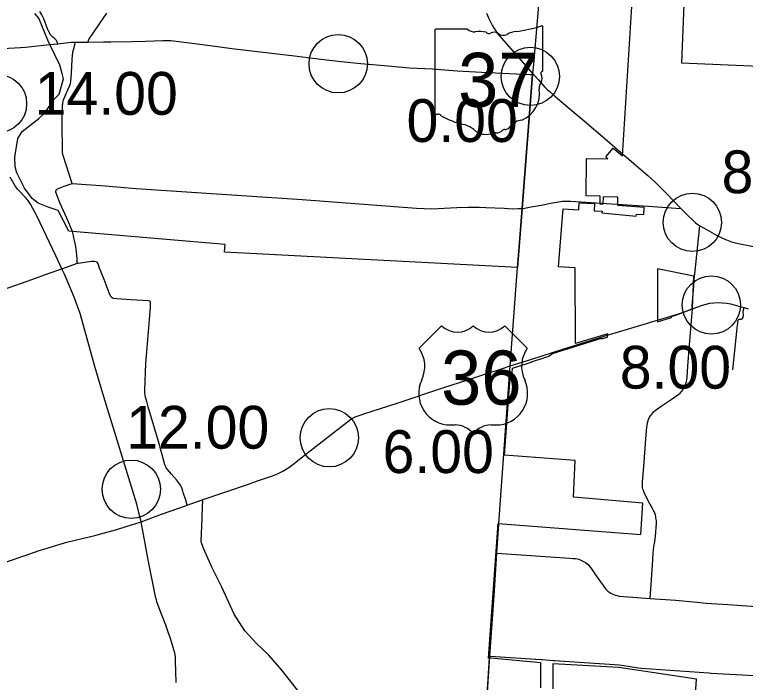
# Model space of a CAD drawing. Extents: x 1597222 to 1925846, y 496284 to 911751.
# Drawn here: x 1780898 to 1799698, y 830013 to 847184 of the extents above; entities that cross this region are included whole.
import ezdxf

# ---------------------------------------------------------------- set-up
doc = ezdxf.new("R2010")
doc.units = 0
for name, color, linetype in [('Default', 7, 'Continuous'), ('GM_X_City_Street', 7, 'Continuous'), ('GM_X_Corporation', 7, 'Continuous'), ('GM_X_County_Road', 7, 'Continuous'), ('GM_X_State_Route', 7, 'Continuous'), ('GM_X_State_Shield', 7, 'Continuous'), ('GM_X_Township', 7, 'Continuous'), ('GM_X_Township_Road', 7, 'Continuous'), ('GM_X_US_Route', 7, 'Continuous'), ('GM_X_US_Shield', 7, 'Continuous')]:
    doc.layers.add(name, color=color, linetype=linetype)

msp = doc.modelspace()

# ---------------------------------------------------------------- linework, layer by layer
at = {"layer": 'Default'}
for centre in [(1789222, 845920), (1794166, 845595), (1780458, 844894), (1798335, 841842), (1798823, 839718), (1788994, 836303), (1783899, 834980)]:
    msp.add_circle(centre, 750, dxfattribs=at)
at = {"layer": 'GM_X_City_Street'}
for points in [[(1797209, 842260), (1797313, 842248), (1798035, 842200)], [(1798391, 840480), (1798393, 840510), (1798525, 841754)], [(1797247, 832172), (1797308, 833027), (1797327, 833333), (1797341, 833506), (1797367, 833630), (1797385, 833772), (1797411, 834102), (1797410, 834129), (1797409, 834165), (1797403, 834211), (1797397, 834244), (1797390, 834277), (1797383, 834312), (1797374, 834341), (1797357, 834387), (1797336, 834430), (1797307, 834485), (1797208, 834668), (1797135, 834807), (1797094, 834887), (1797073, 834944), (1797063, 834978), (1797055, 835013), (1797051, 835044), (1797048, 835076), (1797048, 835124), (1797051, 835173), (1797082, 835564), (1797140, 836270), (1797162, 836583), (1797170, 836630), (1797176, 836667), (1797183, 836695), (1797196, 836742), (1797207, 836777), (1797219, 836804), (1797233, 836833), (1797248, 836861), (1797265, 836886), (1797288, 836914), (1797313, 836944), (1797338, 836971), (1797374, 837003), (1797407, 837026), (1797534, 837113), (1797816, 837304), (1797982, 837420), (1798018, 837451), (1798045, 837481), (1798068, 837511), (1798088, 837537), (1798108, 837569), (1798132, 837611), (1798147, 837650), (1798166, 837697), (1798185, 837753), (1798193, 837803), (1798199, 837862), (1798219, 838143), (1798256, 838693), (1798334, 839621)], [(1798334, 839621), (1798331, 839671)], [(1799374, 838047), (1799488, 839118), (1799511, 839323), (1799525, 839347), (1799540, 839354), (1799586, 839357), (1799611, 839361), (1799640, 839398), (1799646, 839456), (1799643, 839557), (1799664, 839649)], [(1793120, 830695), (1793232, 832236), (1793303, 833333), (1793351, 834085)], [(1793303, 833333), (1795175, 833207), (1795258, 833200), (1795331, 833194), (1795377, 833186), (1795411, 833177), (1795450, 833165), (1795485, 833150), (1795520, 833133), (1795550, 833116), (1795584, 833095), (1795621, 833066), (1795649, 833041), (1795673, 833015), (1795735, 832935), (1795861, 832755), (1796037, 832503), (1796074, 832453), (1796109, 832412), (1796137, 832383), (1796162, 832362), (1796185, 832343), (1796207, 832326), (1796232, 832310), (1796267, 832291), (1796301, 832276), (1796344, 832258), (1796395, 832244), (1796451, 832232), (1796564, 832223), (1796677, 832214), (1796800, 832206), (1797247, 832172), (1797901, 832125), (1798456, 832073), (1798693, 832053), (1799244, 832014), (1800095, 831955)], [(1794436, 830599), (1794466, 830597), (1794751, 830577)], [(1797010, 830375), (1797016, 830374), (1798754, 830257), (1798814, 830253), (1801541, 830101)]]:
    msp.add_lwpolyline(points, dxfattribs=at)
at = {"layer": 'GM_X_Corporation'}
for points in [[(1794432, 829873), (1794432, 830514), (1793153, 830634), (1793153, 830626), (1793093, 830632), (1793335, 834100), (1797009, 833813), (1797057, 834620), (1795274, 834775), (1795316, 835721), (1793499, 835852), (1793659, 837976), (1793698, 837973), (1793707, 838091), (1794085, 838213), (1794212, 838252), (1794209, 838262), (1794434, 838332), (1794637, 838403), (1794733, 838467), (1794733, 838467), (1795997, 838865), (1795996, 838844), (1796153, 838890), (1796155, 838973), (1795326, 838724), (1795319, 840669), (1794894, 840702), (1795009, 842190), (1795409, 842166), (1795420, 842348), (1795817, 842324), (1795804, 842142), (1796013, 842128), (1796009, 842085), (1796891, 842003), (1796893, 842053), (1797088, 842046), (1797094, 842227), (1796414, 842277), (1796416, 842493), (1796036, 842499), (1796033, 842307), (1795958, 842309), (1795961, 842515), (1795598, 842521), (1795613, 843484), (1796162, 843475), (1796105, 843523), (1796297, 843753), (1796540, 843550), (1796878, 849051)], [(1798177, 848946), (1798053, 845944), (1800661, 845836)], [(1798334, 828546), (1798442, 830097), (1796442, 830397), (1794748, 830490), (1794748, 829844)]]:
    msp.add_lwpolyline(points, dxfattribs=at)
msp.add_lwpolyline([(1797441, 839284), (1797798, 839399), (1797801, 839422), (1797912, 839458), (1798198, 839567), (1798339, 839626), (1798371, 840459), (1797440, 840649)], close=True, dxfattribs=at)
at = {"layer": 'GM_X_County_Road'}
for points in [[(1782794, 846480), (1782798, 846516), (1782808, 846543), (1783085, 846950), (1783272, 847226)], [(1793847, 840780), (1793954, 842199), (1794218, 845643)], [(1782409, 841508), (1782391, 841606), (1782242, 841946), (1782072, 842331), (1781962, 842618), (1781962, 842650), (1781965, 842662), (1781975, 842683), (1782000, 842708), (1782174, 842776), (1782382, 842844), (1783229, 842784), (1784027, 842716), (1788298, 842429), (1791241, 842207), (1791633, 842186), (1792271, 842228), (1792567, 842237), (1792853, 842229), (1793017, 842224), (1793496, 842204), (1793598, 842199), (1793716, 842194), (1793856, 842196), (1793901, 842196), (1793954, 842199)], [(1793954, 842199), (1794020, 842207), (1794133, 842230), (1794444, 842288), (1794735, 842342), (1794989, 842386), (1795095, 842389), (1795206, 842386), (1795597, 842359), (1796522, 842302), (1796538, 842301)], [(1796538, 842301), (1796781, 842284), (1797209, 842260)], [(1782516, 840796), (1782504, 840822), (1782504, 840849), (1782503, 840907), (1782496, 840999), (1782473, 841224), (1782437, 841372), (1782421, 841443), (1782409, 841508)], [(1782111, 840650), (1782111, 840650), (1782516, 840796)], [(1793647, 838152), (1793839, 840685), (1793847, 840780)], [(1779079, 839573), (1781342, 840372), (1781765, 840527), (1782111, 840650)], [(1798331, 839671), (1798329, 839693), (1798369, 840209), (1798391, 840480)], [(1793351, 834085), (1793352, 834099), (1793647, 838152)], [(1792915, 827504), (1793116, 830642)], [(1793116, 830642), (1793120, 830695)], [(1793120, 830695), (1793142, 830690), (1794436, 830599)], [(1794751, 830577), (1794787, 830575), (1796457, 830461), (1797010, 830375)]]:
    msp.add_lwpolyline(points, dxfattribs=at)
at = {"layer": 'GM_X_State_Route'}
for points in [[(1794187, 845719), (1793434, 846579), (1793324, 846710), (1793274, 846777), (1793187, 846924), (1793100, 847093), (1793045, 847210)], [(1780260, 846299), (1780260, 846299), (1781047, 846338), (1781176, 846347), (1781331, 846363), (1781806, 846413), (1782009, 846435), (1782350, 846472), (1782467, 846475), (1782747, 846479)], [(1782747, 846479), (1782794, 846480), (1783183, 846484), (1783377, 846485), (1783923, 846492), (1784269, 846503), (1784713, 846520), (1784920, 846517), (1785189, 846487), (1785532, 846441), (1785928, 846388), (1786488, 846310), (1787292, 846217), (1788027, 846133), (1788780, 846042), (1789296, 845980), (1789805, 845926), (1790403, 845872), (1791058, 845819), (1791646, 845786), (1792283, 845741), (1792907, 845707), (1794165, 845645)], [(1794165, 845645), (1794218, 845643), (1794256, 845640)], [(1794256, 845640), (1794225, 845677), (1794187, 845719)], [(1794256, 845640), (1794372, 845506), (1794532, 845328), (1794610, 845252), (1794673, 845195), (1794795, 845090), (1795070, 844854), (1795139, 844795), (1795501, 844493), (1796141, 843947), (1796409, 843716), (1796609, 843541)], [(1796609, 843541), (1796627, 843525), (1796897, 843295), (1796897, 843295)], [(1796897, 843295), (1797184, 843049), (1797375, 842873), (1797459, 842793), (1797671, 842582), (1798035, 842200), (1798181, 842051), (1798372, 841875), (1798417, 841833), (1798475, 841788), (1798525, 841754), (1798715, 841646), (1798952, 841516), (1799123, 841431), (1799251, 841372), (1799337, 841343), (1799378, 841331), (1799477, 841307), (1799775, 841246), (1800109, 841182)], [(1782426, 839915), (1782250, 840350), (1782172, 840527), (1782111, 840650), (1781955, 840981), (1781476, 841997), (1781310, 842306), (1781236, 842414), (1781182, 842481), (1780990, 842678), (1780970, 842699), (1780952, 842720), (1780919, 842766), (1780783, 843002)], [(1785057, 830010), (1785050, 830079), (1785047, 830234), (1785036, 830617), (1785033, 830668), (1785019, 830761), (1784998, 830853), (1784946, 831027), (1784900, 831165), (1784850, 831306), (1784785, 831484), (1784615, 831925), (1784558, 832087), (1784544, 832136), (1784524, 832218), (1784335, 833168), (1784151, 834144), (1784039, 834594), (1783197, 837352), (1782964, 838137), (1782587, 839495), (1782452, 839852), (1782426, 839915)]]:
    msp.add_lwpolyline(points, dxfattribs=at)
at = {"layer": 'GM_X_State_Shield'}
for p, q in [((1791706, 846774), (1791706, 844660)), ((1791706, 846774), (1791706, 844660)), ((1792549, 846810), (1791733, 846810)), ((1792549, 846810), (1791733, 846810)), ((1794490, 845757), (1794490, 846862)), ((1794490, 845757), (1794490, 846862)), ((1794490, 845757), (1794490, 845757)), ((1794490, 845757), (1794490, 845757))]:
    msp.add_line(p, q, dxfattribs=at)
for centre, radius, start, end in [((1791738, 846778), 32.3, 98.1301, 188.1301), ((1791738, 846778), 32.3, 98.1301, 188.1301), ((1792743, 847055), 313, 231.6195, 271.1119), ((1792743, 847055), 313, 231.6195, 271.1119), ((1792846, 845624), 1123, 80.4867, 94.9883), ((1792846, 845624), 1123, 80.4867, 94.9883), ((1793875, 846165), 594, 97.3462, 120.7689), ((1793875, 846165), 594, 97.3462, 120.7689), ((1793498, 849691), 2953, 275.8445, 288.9065), ((1793498, 849691), 2953, 275.8445, 288.9065), ((1794459, 846867), 31, 351.8621, 97.738), ((1794459, 846867), 31, 351.8621, 97.738), ((1793101, 846789), 90.3, 219.7921, 297.1024), ((1793101, 846789), 90.3, 219.7921, 297.1024), ((1793234, 846545), 188, 54.4667, 119.1411), ((1793234, 846545), 188, 54.4667, 119.1411), ((1793476, 846880), 226, 233.8562, 294.8282), ((1793476, 846880), 226, 233.8562, 294.8282), ((1794483, 845676), 48, 107.944, 210.337), ((1794483, 845676), 48, 107.944, 210.337), ((1794178, 845536), 288, 340.033, 23.6496), ((1794178, 845536), 288, 340.033, 23.6496), ((1794457, 845753), 33.2, 289.6038, 7.7341), ((1794457, 845753), 33.2, 289.6038, 7.7341), ((1794601, 845294), 210, 136.8065, 186.9296), ((1794601, 845294), 210, 136.8065, 186.9296), ((1793664, 845154), 739, 292.3089, 8.9858), ((1793664, 845154), 739, 292.3089, 8.9858), ((1791738, 844656), 32.5, 171.9584, 258.3066), ((1791738, 844656), 32.5, 171.9584, 258.3066), ((1791743, 844872), 248, 267.339, 280.6039), ((1791743, 844872), 248, 267.339, 280.6039), ((1791794, 844539), 89.5, 29.7484, 93.2717), ((1791794, 844539), 89.5, 29.7484, 93.2717), ((1792924, 846437), 2132, 240.4129, 257.1985), ((1792924, 846437), 2132, 240.4129, 257.1985), ((1792288, 843711), 667, 47.1842, 75.836), ((1792288, 843711), 667, 47.1842, 75.836), ((1793463, 844456), 239, 282.8732, 323.2771), ((1793463, 844456), 239, 282.8732, 323.2771), ((1793975, 844067), 404, 94.4031, 142.5768), ((1793975, 844067), 404, 94.4031, 142.5768), ((1793010, 844528), 423, 230.7004, 286.2918), ((1793010, 844528), 423, 230.7004, 286.2918), ((1793255, 843797), 348, 85.6951, 111.2099), ((1793255, 843797), 348, 85.6951, 111.2099), ((1793286, 844370), 226, 268.777, 315.5493), ((1793286, 844370), 226, 268.777, 315.5493), ((1793490, 844165), 63.5, 65.7517, 132.6484), ((1793490, 844165), 63.5, 65.7517, 132.6484)]:
    msp.add_arc(centre, radius, start, end, dxfattribs=at)
at = {"layer": 'GM_X_Township'}
for points in [[(1794528, 849265), (1794250, 845913), (1794225, 845677), (1794218, 845643), (1793954, 842199), (1793839, 840685), (1786300, 841075), (1786314, 841270), (1782391, 841606), (1782290, 841614), (1782021, 842150), (1781758, 842232), (1781508, 842340), (1781351, 842454), (1781155, 842721), (1780952, 843117), (1780916, 843270), (1780907, 843520), (1780980, 844003), (1781094, 844181), (1781518, 844515), (1781682, 844666), (1781918, 845013), (1782045, 845142), (1782155, 845534), (1782125, 845674), (1782062, 845883), (1781806, 846413), (1781752, 846525), (1781519, 847094), (1781420, 847210)], [(1792915, 827502), (1793120, 830695), (1793232, 832236), (1793303, 833333), (1793352, 834099), (1793647, 838152), (1793839, 840685)]]:
    msp.add_lwpolyline(points, dxfattribs=at)
at = {"layer": 'GM_X_Township_Road'}
for points in [[(1782009, 846435), (1781994, 846482), (1781973, 846515), (1781956, 846538), (1781929, 846565), (1781890, 846597), (1781839, 846644), (1781814, 846675), (1781792, 846718), (1781744, 846822), (1781649, 847077), (1781600, 847179), (1781548, 847266)], [(1782382, 842844), (1782151, 843564), (1782126, 843641), (1782122, 844417), (1782128, 844831), (1782131, 844863), (1782135, 844894), (1782148, 844956), (1782159, 844992), (1782295, 845310), (1782307, 845335), (1782325, 845387), (1782332, 845413), (1782342, 845467), (1782359, 845678), (1782380, 846027), (1782397, 846217), (1782411, 846275), (1782467, 846475)], [(1785341, 834572), (1785304, 834696), (1785235, 834898), (1785228, 834929), (1785208, 834991), (1785183, 835051), (1785168, 835080), (1785144, 835122), (1785062, 835221), (1784931, 835371), (1784829, 835487), (1784800, 835530), (1784787, 835552), (1784776, 835576), (1784765, 835603), (1784625, 836119), (1784338, 837095), (1784296, 837239), (1784255, 837382), (1784244, 837484), (1784244, 837528), (1784276, 838215), (1784330, 838924), (1784391, 839658), (1784395, 839783), (1784389, 839805), (1784374, 839815), (1784341, 839823), (1783889, 839850), (1783530, 839873), (1783431, 839887), (1783405, 839902), (1783381, 839921), (1783363, 839952), (1783330, 840034), (1783198, 840371), (1783084, 840668), (1783045, 840772), (1783019, 840816), (1782989, 840831), (1782941, 840838), (1782879, 840837), (1782530, 840785), (1782516, 840796)], [(1788621, 827994), (1788650, 828063), (1788726, 828178), (1788739, 828252), (1788721, 828512), (1788707, 828711), (1788718, 828879), (1788680, 829037), (1788510, 829354), (1788376, 829562), (1787776, 830325), (1787442, 830711), (1787118, 831016), (1786817, 831334), (1786550, 831763), (1786230, 832458), (1785968, 832975), (1785767, 833439), (1785710, 833597), (1785701, 833646), (1785722, 834226), (1785735, 834569), (1785736, 834651), (1785723, 834708)]]:
    msp.add_lwpolyline(points, dxfattribs=at)
at = {"layer": 'GM_X_US_Route'}
for points in [[(1797279, 839280), (1797440, 839329), (1797949, 839483), (1798026, 839508), (1798154, 839553), (1798334, 839621)], [(1798334, 839621), (1798449, 839665), (1798596, 839716), (1798693, 839742), (1798786, 839760), (1798883, 839772), (1799014, 839778), (1799098, 839777), (1799221, 839764), (1799313, 839748), (1799413, 839724), (1799529, 839690), (1799664, 839649), (1799768, 839617)], [(1796520, 839053), (1796580, 839071), (1797177, 839250)], [(1797177, 839250), (1797279, 839280)], [(1796115, 838930), (1796520, 839053)], [(1794201, 838327), (1794977, 838574), (1796065, 838914)], [(1796065, 838914), (1796113, 838930), (1796115, 838930)], [(1793596, 838135), (1793647, 838152), (1794201, 838327)], [(1793294, 838037), (1793503, 838105), (1793596, 838135)], [(1785291, 834555), (1785341, 834572), (1785723, 834708), (1786913, 835110), (1787149, 835192), (1787535, 835324), (1787660, 835373), (1787802, 835441), (1787953, 835536), (1788092, 835640), (1788316, 835821), (1788577, 836027), (1789200, 836511), (1789464, 836715), (1789512, 836752), (1789559, 836786), (1789581, 836800), (1789608, 836815), (1789657, 836839), (1789708, 836860), (1789760, 836879), (1789880, 836917), (1790713, 837188), (1791944, 837592), (1792535, 837787), (1793152, 837991), (1793294, 838037)], [(1784151, 834144), (1784673, 834334), (1785291, 834555)], [(1781140, 833266), (1781530, 833400), (1781652, 833441), (1782073, 833569), (1782240, 833615), (1782816, 833759), (1782964, 833793), (1783306, 833880), (1783524, 833942), (1783770, 834017), (1784151, 834144)], [(1773271, 830397), (1773379, 830444), (1774387, 830877), (1775615, 831340), (1776007, 831488), (1777883, 832171), (1778258, 832305), (1778909, 832522), (1779520, 832725), (1780843, 833166), (1781136, 833265), (1781140, 833266)]]:
    msp.add_lwpolyline(points, dxfattribs=at)
at = {"layer": 'GM_X_US_Shield'}
for p, q in [((1791884, 839184), (1791304, 838604)), ((1791884, 839184), (1791304, 838604)), ((1794088, 838604), (1793508, 839184)), ((1794088, 838604), (1793508, 839184)), ((1792116, 836632), (1792232, 836632)), ((1792116, 836632), (1792232, 836632)), ((1793160, 836632), (1793276, 836632)), ((1793160, 836632), (1793276, 836632))]:
    msp.add_line(p, q, dxfattribs=at)
for centre, radius, start, end in [((1792290, 839599), 580, 225.573, 314.427), ((1792290, 839599), 580, 225.573, 314.427), ((1793102, 839599), 580, 225.573, 314.427), ((1793102, 839599), 580, 225.573, 314.427), ((1790639, 838139), 812, 334.5471, 35.0009), ((1790639, 838139), 812, 334.5471, 35.0009), ((1794753, 838139), 812, 144.9991, 205.4529), ((1794753, 838139), 812, 144.9991, 205.4529), ((1792107, 837444), 812, 154.8319, 270.6383), ((1792107, 837444), 812, 154.8319, 270.6383), ((1793285, 837444), 812, 269.3617, 25.1681), ((1793285, 837444), 812, 269.3617, 25.1681), ((1792232, 836052), 580, 36.8699, 90), ((1792232, 836052), 580, 36.8699, 90), ((1793160, 836052), 580, 90, 143.1301), ((1793160, 836052), 580, 90, 143.1301)]:
    msp.add_arc(centre, radius, start, end, dxfattribs=at)

# ---------------------------------------------------------------- texts
at = {"layer": 'Default'}
for s, p in [('14.00', (1781415, 844608)), ('0.00', (1790981, 843910)), ('8.00', (1799085, 842592)), ('8.00', (1796467, 837567)), ('12.00', (1783768, 836024)), ('6.00', (1790365, 835396))]:
    msp.add_text(s, height=1100, dxfattribs=at).set_placement(p)
at = {"layer": 'GM_X_State_Shield'}
msp.add_text('37', height=1392.2, dxfattribs=at).set_placement((1792306, 844810))
msp.add_text('37', height=1392.2, dxfattribs=at).set_placement((1792306, 844810))
at = {"layer": 'GM_X_US_Shield'}
msp.add_text('36', height=1392.2, dxfattribs=at).set_placement((1791868, 837154))
msp.add_text('36', height=1392.2, dxfattribs=at).set_placement((1791868, 837154))

doc.saveas('drawing.dxf')
